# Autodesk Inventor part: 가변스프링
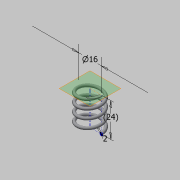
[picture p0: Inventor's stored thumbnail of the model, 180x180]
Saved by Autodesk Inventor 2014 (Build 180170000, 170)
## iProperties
Created: 2015-04
Part Number: 가변스프링
Material: 강철, 탄소
Document SubType Name: Modeling
Designer: Administrator
Mass: 4.78551 g
Surface Area: 12.5277 cm^2
Volume: 0.60807 cm^3
Density: 7.87 g/cm^3
Appearance: 반연마
Author: Administrator
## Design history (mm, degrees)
sketch "스케치1"
  geometry: L1 (0, 0)-(8, 0); L2 (8, 0)-(8, 11.5); L3 (8, 11.5)-(0, 11.5); L4 (0, 11.5)-(0, 0); C1 r 1 at (8, 0)
  constraints: 8 end point, 2 parallel, 1 centre point, 1 coincident, 1 horizontal, 1 perpendicular
  dimensions: "d0" = 16 diameter of L2 L4; "d1" = 11.50049 distance between parallel lines of L1 L3 (derived); "d2" = 2 diameter of C1
feature "코일1" pitch "d3" = 10; turns "d5" = 4; dims "d4" = 11.50049 (= d1), "d6" = 0, angle "d7" = 90 deg, angle "d8" = 90 deg, "d9" = 0, "d10" = 0
sketch "스케치2"
  geometry: L1 (-9, 0)-(-7, 0) reference; 1 further point
  constraints: 1 horizontal alignment
extrude "돌출1" cut sketch "스케치2" stored distance "d11" = 10; taper "d12" = 0 deg
node "작업 평면1"
sketch "스케치3"
  geometry: L1 (9, 0)-(7, 0) reference; 1 further point
  constraints: 1 horizontal alignment
extrude "돌출2" cut sketch "스케치3" stored distance "d13" = 10; taper "d14" = 0 deg
node "솔리드1"
node "절단 모서리 투영1"
node "절단 모서리 투영2"
